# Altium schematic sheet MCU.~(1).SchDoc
size A3
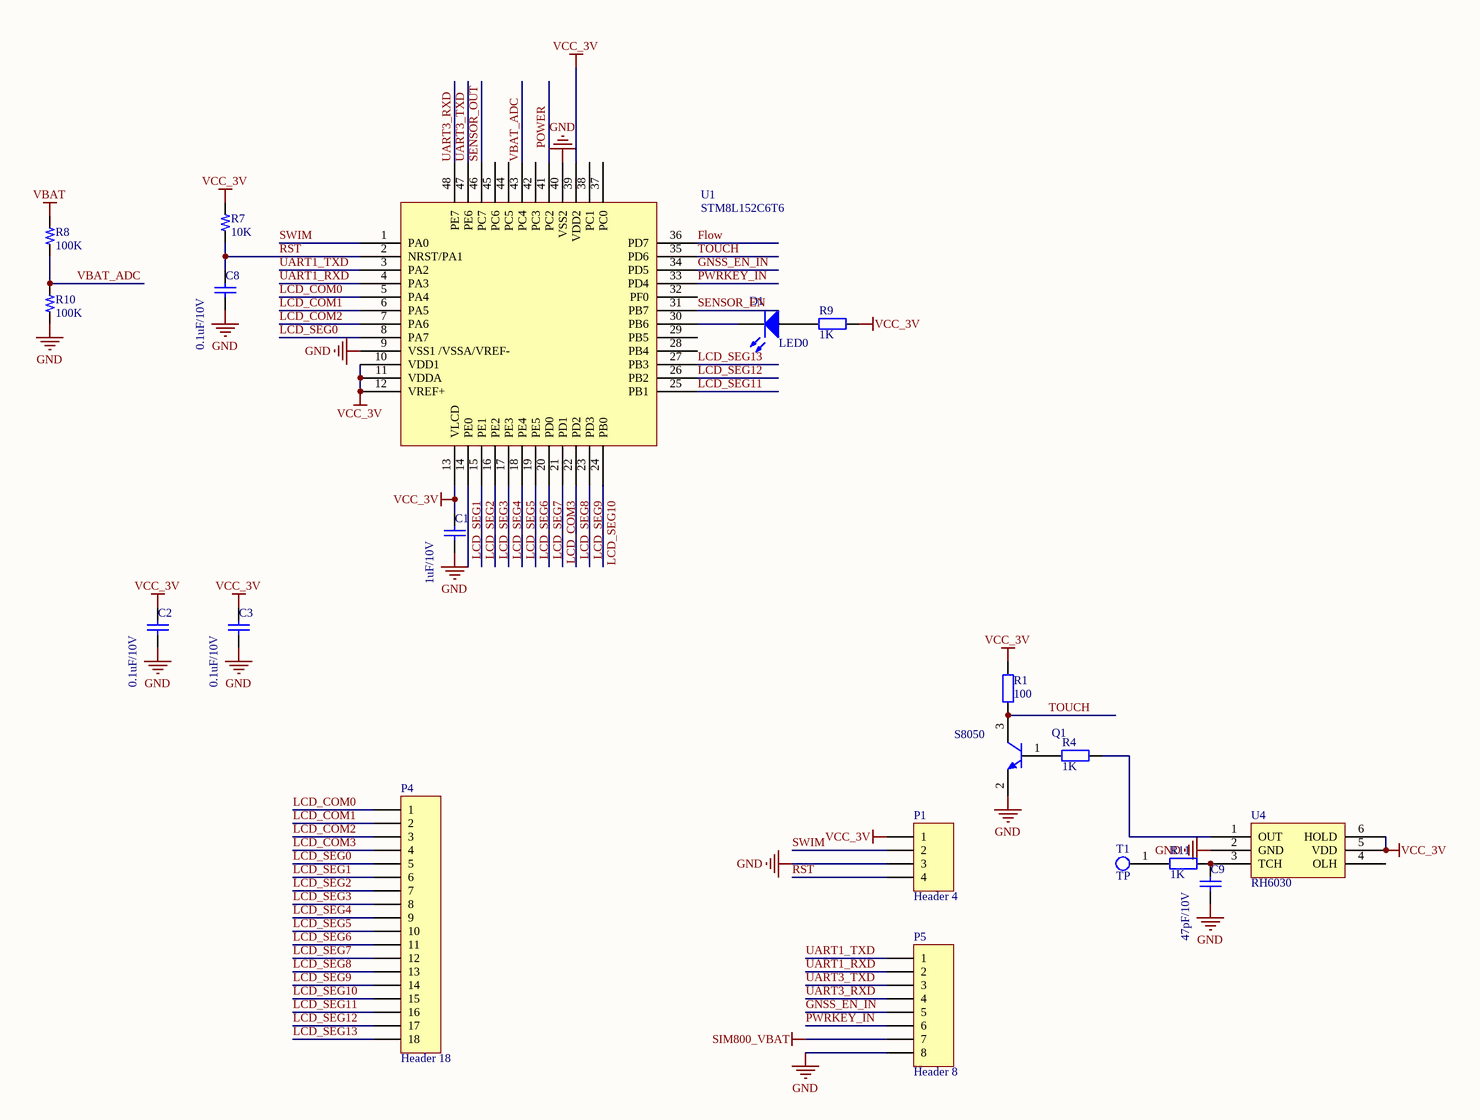
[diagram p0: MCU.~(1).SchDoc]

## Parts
C1  1uF/10V  [0603C]
C2  0.1uF/10V  [0603C]
C3  0.1uF/10V  [0603C]
C8  0.1uF/10V  [0603C]
C9  47pF/10V  [0603C]
D1  LED0  [0603LED]
P1  Header 4  [HDR1X4]
P4  Header 18  [lcd]
P5  Header 8  [HDR1X8]
Q1  S8050  [SOT23-3]
R1  100  [0603R]
R4  1K  [0603R]
R7  10K  [0603R]
R8  100K  [0603R]
R9  1K  [0603R]
R10  100K  [0603R]
R11  1K  [0603R]
T1  TP  [TOUCH-PAD]
U1  STM8L152C6T6  [TQFP-48]
U4  RH6030  [SOT-23-6]

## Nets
GND: C1.2 C2.2 C3.2 C8.2 C9.2 P1.3 P5.8 Q1.2(E) R10.1 U1.9(VSS1_/VSSA/VREF-) U1.40(VSS2) U4.2(GND)
SIM800_VBAT: P5.7
VBAT: R8.2
VCC_3V: C1.1 C2.1 C3.1 P1.1 R1.1 R7.2 R9.1 U1.10(VDD1) U1.11(VDDA) U1.12(VREF+) U1.13(VLCD) U1.39(VDD2) U4.5(VDD) U4.6(HOLD)
Flow: U1.36(PD7)
GNSS_EN_IN: P5.5 U1.34(PD5)
LCD_COM0: P4.1 U1.5(PA4)
LCD_COM1: P4.2 U1.6(PA5)
LCD_COM2: P4.3 U1.7(PA6)
LCD_COM3: P4.4 U1.21(PD1)
LCD_SEG0: P4.5 U1.8(PA7)
LCD_SEG1: P4.6 U1.14(PE0)
LCD_SEG2: P4.7 U1.15(PE1)
LCD_SEG3: P4.8 U1.16(PE2)
LCD_SEG4: P4.9 U1.17(PE3)
LCD_SEG5: P4.10 U1.18(PE4)
LCD_SEG6: P4.11 U1.19(PE5)
LCD_SEG7: P4.12 U1.20(PD0)
LCD_SEG8: P4.13 U1.22(PD2)
LCD_SEG9: P4.14 U1.23(PD3)
LCD_SEG10: P4.15 U1.24(PB0)
LCD_SEG11: P4.16 U1.25(PB1)
LCD_SEG12: P4.17 U1.26(PB2)
LCD_SEG13: P4.18 U1.27(PB3)
POWER: U1.41(PC2)
PWRKEY_IN: P5.6 U1.33(PD4)
RST: C8.1 P1.4 R7.1 U1.2(NRST/PA1)
SENSOR_EN: U1.31(PB7)
SENSOR_OUT: U1.46(PC7)
SWIM: P1.2 U1.1(PA0)
TOUCH: Q1.3(C) R1.2 U1.35(PD6)
UART1_RXD: P5.2 U1.4(PA3)
UART1_TXD: P5.1 U1.3(PA2)
UART3_RXD: P5.4 U1.48(PE7)
UART3_TXD: P5.3 U1.47(PE6)
VBAT_ADC: R8.1 R10.2 U1.43(PC4)
NetC9_1: C9.1 R11.1 U4.3(TCH)
NetD1_1: D1.1(A) R9.2
NetD1_2: D1.2(K) U1.30(PB6)
NetQ1_1: Q1.1(B) R4.2
NetR4_1: R4.1 U4.1(OUT)
NetR11_2: R11.2 T1.1

Not connected (* = marked no-connect by the designer): U1 28(PB4) 29(PB5) 32(PF0) 37(PC0) 38(PC1) 42(PC3) 44(PC5) 45(PC6); U4 4(OLH)

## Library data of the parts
C1-C3 C8 C9 = Cap: Capacitor; Value: 104
D1 = LED0: Typical INFRARED GaAs LED
P1 = Header 4: Header, 4-Pin
P4 = Header 18: Header, 18-Pin
P5 = Header 8: Header, 8-Pin
Q1 = NPN
R1 = Res2: Resistor; Value: 1K
R4 R9 R11 = Res2: Resistor
R7 R8 R10 = R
